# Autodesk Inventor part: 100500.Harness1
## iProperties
GlobalPropertyList: <PropertyList><Property propid="Custom" name="desc1" type="14107" originalName="DESC1"/><Property propid="Custom" name="desc2" type="14107" originalName="DESC2"
Key:2|1|1|0|4|0|0|0|57|0|0|0|Level:2: <CableProperty entityType="Connector" version="1.0"><ID editable="" value=""/><UserDefined><Property name="DESC1" value="HORIZONTAL" unitCategory="14107" custom
Key:2|1|1|0|4|0|0|0|58|0|0|0|Level:2: <CableProperty entityType="Connector" version="1.0"><ID editable="" value=""/><UserDefined><Property name="DESC1" value="REAR VERTICAL" unitCategory="14107" cus
Key:2|1|1|0|4|0|0|0|56|0|0|0|Level:2: <CableProperty entityType="Connector" version="1.0"><ID editable="" value=""/><UserDefined><Property name="DESC1" value="FRONT VERTICAL" unitCategory="14107" cu
Key:2|1|1|0|4|0|0|0|55|0|0|0|Level:2: <CableProperty entityType="Connector" version="1.0"><ID editable="" value=""/><UserDefined><Property name="DESC1" value="POWER SEAT" unitCategory="14107" custom
Key:2|1|1|0|4|0|0|0|59|0|0|0|Level:2: <CableProperty entityType="Connector" version="1.0"><ID editable="" value=""/><UserDefined><Property name="DESC1" value="POWER FOR SEAT" unitCategory="14107" cu
Created: 2009-02
Part Number: 100500.Harness1
Document SubType Name: Modeling
Designer: Autodesk
Author: Autodesk
